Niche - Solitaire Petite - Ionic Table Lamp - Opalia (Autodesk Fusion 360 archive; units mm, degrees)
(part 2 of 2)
derived_base_feature "Derived Base Feature" bodies "E26 Base"
named bodies: "E26 Base"

design "Chinois"
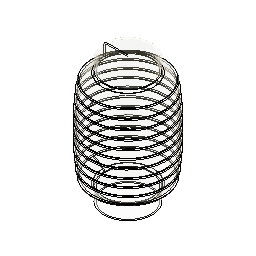
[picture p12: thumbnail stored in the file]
named bodies: "Chinois"

design "2-Pole Plug End"
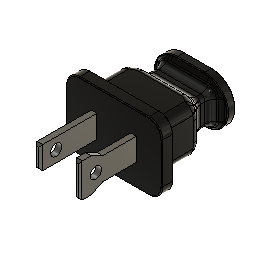
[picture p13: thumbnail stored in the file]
sketch "Sketch1" plane through (0, 0, 0) normal (0, 1, 0) x axis (1, 0, 0)
  line L1 (9.6837, 9.525) -> (-9.6837, 9.525)
  line L2 (13.4938, -5.715) -> (13.4938, 5.715)
  line L3 (-9.6837, -9.525) -> (9.6837, -9.525)
  line L4 (-13.4937, 5.715) -> (-13.4937, -5.715)
  line L5 (13.4938, -9.525) -> (-13.4937, 9.525)
  line L6 (-13.4937, -9.525) -> (13.4938, 9.525)
  arc A1 centre (-9.6837, -5.715) radius 3.81 clockwise from (-9.6837, -9.525) to (-13.4937, -5.715)
  arc A2 centre (9.6837, -5.715) radius 3.81 clockwise from (13.4938, -5.715) to (9.6837, -9.525)
  arc A3 centre (9.6837, 5.715) radius 3.81 clockwise from (9.6837, 9.525) to (13.4938, 5.715)
  arc A4 centre (-9.6837, 5.715) radius 3.81 clockwise from (-13.4937, 5.715) to (-9.6837, 9.525)
  point P6 (0, 0)
  point P1 (0, 0)
  point P5 (-13.4937, -9.525)
  point P4 (13.4938, -9.525)
  point P3 (13.4938, 9.525)
  point P2 (-13.4937, 9.525)
  horizontal L1
  perpendicular L1 L2
  parallel L1 L3
  parallel L2 L4
  coincident L5 P6
  coincident L6 P6
  coincident P1 P6
  coincident P5 L4
  coincident P5 L3
  tangent L4 A1
  tangent L3 A1
  coincident P4 L3
  coincident P4 L2
  tangent L3 A2
  tangent L2 A2
  equal A1 A2
  coincident P3 L2
  coincident P3 L1
  tangent L2 A3
  tangent L1 A3
  equal A1 A3
  coincident P2 L1
  coincident P2 L4
  tangent L1 A4
  tangent L4 A4
  equal A1 A4
  dimension "d1" distance P4 P5 = 26.9875
  dimension "d2" distance P2 P5 = 19.05
  dimension "d3" radius A1 = 3.81
extrude "Extrude1" new body sketch "Sketch1" profile of L1 L2 L3 L4 A1 A2 A3 A4 along normal blind 3.175
sketch "Sketch2" plane through (0, 3.175, 0) normal (0, 1, 0) x axis (-1, 0, 0)
  line L1 (9.6837, -9.525) -> (-9.6837, -9.525)
  line L2 (13.4937, 5.715) -> (13.4937, -5.715)
  line L3 (-9.6837, 9.525) -> (9.6837, 9.525)
  line L4 (-13.4938, -5.715) -> (-13.4938, 5.715)
  line L5 (10.16, -6.35) -> (-10.16, -6.35)
  line L6 (10.16, 6.35) -> (10.16, -6.35)
  line L7 (-10.16, 6.35) -> (10.16, 6.35)
  line L8 (-10.16, -6.35) -> (-10.16, 6.35)
  line L9 (10.16, 6.35) -> (-10.16, -6.35)
  line L10 (-10.16, 6.35) -> (10.16, -6.35)
  arc A1 centre (-9.6837, -5.715) radius 3.81 clockwise from (-9.6837, -9.525) to (-13.4938, -5.715)
  arc A2 centre (9.6837, -5.715) radius 3.81 clockwise from (13.4937, -5.715) to (9.6837, -9.525)
  arc A3 centre (9.6837, 5.715) radius 3.81 clockwise from (9.6837, 9.525) to (13.4937, 5.715)
  arc A4 centre (-9.6837, 5.715) radius 3.81 clockwise from (-13.4938, 5.715) to (-9.6837, 9.525)
  point P18 (0, 0)
  point P1 (0, 0)
  horizontal L5
  perpendicular L5 L6
  parallel L5 L7
  parallel L6 L8
  coincident L9 P18
  coincident L10 P18
  coincident P1 P18
extrude "Extrude2" add sketch "Sketch2" profile of L5 L6 L7 L8 along normal blind 9.525
sketch "Sketch3" plane through (0, 12.7, 0) normal (0, 1, 0) x axis (-1, 0, 0)
  line L1 (-10.16, -6.35) -> (-10.16, 6.35)
  line L2 (10.16, -6.35) -> (-10.16, -6.35)
  line L3 (10.16, 6.35) -> (10.16, -6.35)
  line L4 (-10.16, 6.35) -> (10.16, 6.35)
  line L5 (-7.1437, 3.9688) -> (7.1437, 3.9688)
  line L6 (-7.1437, -3.9688) -> (-7.1437, 3.9688)
  line L7 (7.1437, -3.9688) -> (-7.1437, -3.9688)
  line L8 (7.1437, 3.9688) -> (7.1437, -3.9688)
  line L9 (-7.1437, -3.9688) -> (7.1437, 3.9688)
  line L10 (7.1437, -3.9688) -> (-7.1437, 3.9688)
  point P10 (0, 0)
  point P1 (0, 0)
  point P8 (-7.1437, -3.9688)
  point P9 (7.1437, -3.9688)
  point P7 (-7.1437, 3.9688)
  horizontal L5
  perpendicular L5 L6
  parallel L5 L7
  parallel L6 L8
  coincident L9 P10
  coincident L10 P10
  coincident P1 P10
  dimension "d8" distance P8 P9 = 14.2875
  dimension "d9" distance P7 P8 = 7.9375
extrude "Extrude3" add sketch "Sketch3" profile of L5 L6 L7 L8 along normal blind 11.1125
fillet "Fillet1" radius 2.286 1.27 0.254
chamfer "Chamfer1" distance 3.429
fillet "Fillet2" radius 2.54 1.905
sketch "Sketch4" plane through (0, 23.8125, 0) normal (0, 1, 0) x axis (-1, 0, 0)
  line L1 (-7.1437, -2.6987) -> (-7.1437, 2.6987)
  line L2 (5.8737, -3.9688) -> (-5.8737, -3.9688)
  line L3 (7.1437, 2.6987) -> (7.1437, -2.6987)
  line L4 (-5.8737, 3.9688) -> (5.8737, 3.9688)
  line L5 (-3.81, 6.604) -> (3.81, 6.604)
  line L6 (3.81, -6.604) -> (-3.81, -6.604)
  line L7 (-10.414, 0) -> (10.414, 0)
  arc A1 centre (-5.8737, 2.6987) radius 1.27 clockwise from (-7.1437, 2.6987) to (-5.8737, 3.9688)
  arc A2 centre (-5.8737, -2.6987) radius 1.27 clockwise from (-5.8737, -3.9688) to (-7.1437, -2.6987)
  arc A3 centre (5.8737, -2.6987) radius 1.27 clockwise from (7.1437, -2.6987) to (5.8737, -3.9688)
  arc A4 centre (5.8737, 2.6987) radius 1.27 clockwise from (5.8737, 3.9688) to (7.1437, 2.6987)
  arc A5 centre (-3.81, 0) radius 6.604 clockwise from (-3.81, -6.604) to (-3.81, 6.604)
  arc A6 centre (3.81, 0) radius 6.604 clockwise from (3.81, 6.604) to (3.81, -6.604)
  point P20 (10.414, 0)
  point P21 (-10.414, 0)
  tangent L5 A5
  tangent A5 L6
  parallel L5 L6
  tangent L6 A6
  tangent L5 A6
  midpoint A6 P20
  midpoint A5 P21
  perpendicular L1 L7
extrude "Extrude4" add sketch "Sketch4" profile of A1 L1 A2 L2 A3 L3 A4 L4 L5 A5 L6 A6 against normal blind 2.286
chamfer "Chamfer2" distance 1.778
fillet "Fillet3" radius 1.778
fillet "Fillet4" radius 0.254
fillet "Fillet5" radius 0.254
fillet "Fillet6" radius 0.254
fillet "Fillet7" radius 3.175
sketch "Sketch5" plane through (0, 0, 0) normal (0, -1, 0) x axis (1, 0, 0)
  line L1 (-13.2397, -5.715) -> (-13.2397, 5.715)
  line L2 (9.6837, -9.271) -> (-9.6837, -9.271)
  line L3 (13.2397, 5.715) -> (13.2397, -5.715)
  line L4 (-9.6837, 9.271) -> (9.6837, 9.271)
  line L5 (-6.35, -3.175) -> (-6.35, 3.175)
  line L6 (6.35, 3.175) -> (-6.35, -3.175)
  line L7 (-6.35, 3.175) -> (6.35, -3.175)
  line L8 (-4.7625, 3.175) -> (-6.35, 3.175)
  line L9 (-4.7625, -3.175) -> (-4.7625, 3.175)
  line L10 (-6.35, -3.175) -> (-4.7625, -3.175)
  line L11 (-6.35, 3.175) -> (-6.35, -3.175)
  line L12 (0, -3.302) -> (0, 3.81)
  line L13 (4.7625, -3.175) -> (4.7625, 3.175)
  line L14 (4.7625, 3.175) -> (6.35, 3.175)
  line L15 (6.35, -3.175) -> (6.35, 3.175)
  line L16 (6.35, -3.175) -> (4.7625, -3.175)
  arc A1 centre (-9.6837, 5.715) radius 3.556 clockwise from (-13.2397, 5.715) to (-9.6837, 9.271)
  arc A2 centre (-9.6837, -5.715) radius 3.556 clockwise from (-9.6837, -9.271) to (-13.2397, -5.715)
  arc A3 centre (9.6837, -5.715) radius 3.556 clockwise from (13.2397, -5.715) to (9.6837, -9.271)
  arc A4 centre (9.6837, 5.715) radius 3.556 clockwise from (9.6837, 9.271) to (13.2397, 5.715)
  point P18 (0, 0)
  point P1 (0, 0)
  point P14 (-6.35, -3.175)
  point P27 (6.35, -3.175)
  point P17 (-6.35, 3.175)
  point P26 (6.35, 3.175)
  point P19 (-4.7625, 3.175)
  point P24 (4.7625, 3.175)
  point P20 (-4.7625, -3.175)
  point P25 (4.7625, -3.175)
  point P21 (-6.35, -3.175)
  point P28 (6.35, -3.175)
  point P15 (6.35, -3.175)
  point P16 (6.35, 3.175)
  coincident L6 P18
  coincident L7 P18
  coincident P1 P18
  horizontal L8
  vertical L9
  horizontal L10
  vertical L11
  vertical L12
  symmetric P14 L12 P27
  symmetric P17 L12 P26
  symmetric P19 L12 P24
  symmetric P20 L12 P25
  symmetric P21 L12 P28
  dimension "d36" distance P15 P16 = 6.35
  dimension "d37" distance P17 P19 = 1.5875
extrude "Extrude5" add sketch "Sketch5" profile of L5 L8 L9 L10 L11 L13 L14 L15 L16 along normal blind 15.875
sketch "Sketch7" plane through (0, 0, 3.175) normal (0, 0, 1) x axis (-1, 0, 0)
  line L1 (-4.7625, 0) -> (-6.35, 0)
  line L2 (-4.7625, 15.875) -> (-4.7625, 0)
  line L3 (-6.35, 15.875) -> (-4.7625, 15.875)
  line L4 (-6.35, 0) -> (-6.35, 15.875)
  line L5 (-4.7625, 15.875) -> (-6.35, 15.875)
  line L6 (-4.7625, 9.525) -> (-4.7625, 15.875)
  line L7 (-6.35, 9.525) -> (-4.7625, 9.525)
  line L8 (-6.35, 15.875) -> (-6.35, 9.525)
  point P5 (-6.35, 15.875)
  point P6 (-6.35, 15.875)
  point P9 (-6.35, 9.525)
  horizontal L5
  vertical L6
  horizontal L7
  vertical L8
  coincident P5 P6
  dimension "d45" distance P6 P9 = 6.35
extrude "Extrude7" add sketch "Sketch7" profile of L2 L3 L4 L5 L6 L7 L8 against normal blind 7.9375 and along normal blind 1.5875
chamfer "Chamfer3" distance 0.508
chamfer "Chamfer4" distance 0.635 distance 0.635
sketch "Sketch6" plane through (6.35, 0, 0) normal (1, 0, 0) x axis (0, 1, 0)
  line L1 (0, -3.175) -> (-9.525, -3.175)
  line L2 (0, 3.175) -> (0, -3.175)
  line L3 (-9.525, 3.175) -> (0, 3.175)
  line L4 (-15.367, -4.6355) -> (-15.367, 4.6355)
  line L5 (-11.43, 0) -> (-16.002, 0)
  line L6 (-9.525, -4.7625) -> (-15.24, -4.7625)
  line L7 (-9.525, -3.175) -> (-9.525, -4.7625)
  line L8 (-9.525, 4.7625) -> (-9.525, 3.175)
  line L9 (-15.24, 4.7625) -> (-9.525, 4.7625)
  line L10 (-15.24, -4.7625) -> (-15.367, -4.6355)
  line L11 (-15.367, 4.6355) -> (-15.24, 4.7625)
  circle C1 centre (-11.43, 0) radius 1.5875
  point P9 (-11.43, 0)
  point P10 (-11.43, 0)
  perpendicular L4 L5
  coincident P9 P10
  dimension "d42" diameter C1 = 3.175
extrude "Extrude6" cut sketch "Sketch6" profile of C1 against normal blind 20.32
chamfer "Chamfer5" distance 3.175 distance 1.5875 distance 3.175 distance 1.5875
component_from_bodies "Body->Comp"
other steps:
base_feature "Base Feature" bodies "2-Pole Plug End"
create_component "CreateComponent1"
remove_body "RemoveBody1"
named bodies: "2-Pole Plug End"

design "Marble Base - Plastic Insert"
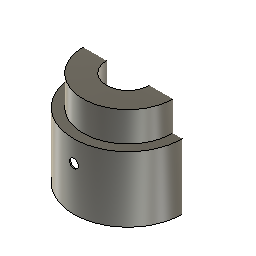
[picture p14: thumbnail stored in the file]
sketch "Sketch1" plane through (0, 0, 0) normal (0, 0, 1) x axis (1, 0, 0)
  circle C1 centre (0, 0) radius 50.038
  point P1 (0, 0)
  point P2 (0, 0)
  coincident P1 P2
  dimension "d1" diameter C1 = 100.076
extrude "Extrude1" new body sketch "Sketch1" along normal blind 72.898 bodies "Plastic Insert"
shell "Shell1" innerThickness 1.016
work_plane "WorkPlane1" AlongDistance 18.034
sketch "Sketch2" plane through (0, 0, 90.932) normal (0, 0, 1) x axis (1, 0, 0)
  circle C1 centre (0, 0) radius 20.701
  point P1 (0, 0)
  point P2 (0, 0)
  coincident P1 P2
  dimension "d6" diameter C1 = 41.402
extrude "Extrude2" add sketch "Sketch2" against normal blind 65.024
shell "Shell2" innerThickness 1.016
sketch "Sketch3" plane through (0, 0, 0) normal (0, 1, 0) x axis (1, 0, 0)
  line L1 (5.08, -20.32) -> (-5.08, -20.32)
  line L2 (5.08, 20.32) -> (5.08, -20.32)
  line L3 (-5.08, 20.32) -> (5.08, 20.32)
  line L4 (-5.08, -20.32) -> (-5.08, 20.32)
  line L5 (5.08, 20.32) -> (-5.08, -20.32)
  line L6 (-5.08, 20.32) -> (5.08, -20.32)
  point P6 (0, 0)
  point P1 (0, 0)
  horizontal L1
  perpendicular L1 L2
  parallel L1 L3
  parallel L2 L4
  coincident L5 P6
  coincident L6 P6
  coincident P1 P6
extrude "Extrude3" cut sketch "Sketch3" profile of L1 L2 L3 L4 along normal blind 91.44
sketch "Sketch4" plane through (0, 0, 0) normal (0, 1, 0) x axis (1, 0, 0)
  line L1 (0, -40.64) -> (0, 0)
  circle C1 centre (0, -40.64) radius 4.064
  point P1 (0, 0)
  point P2 (0, 0)
  point P3 (0, -40.64)
  point P4 (0, -40.64)
  coincident P1 P2
  vertical L1
  coincident P3 P4
  dimension "d12" diameter C1 = 8.128
work_plane "WorkPlane2" AlongDistance -91.44
sketch "Sketch5" plane through (0, -91.44, 0) normal (0, 1, 0) x axis (1, 0, 0)
  circle C1 centre (0, -40.64) radius 4.064
extrude "Extrude4" cut sketch "Sketch5" along normal blind 63.5
sketch "Sketch6" plane through (0, 0, 26.924) normal (0, 0, 1) x axis (-1, 0, 0)
  circle C1 centre (0, 0) radius 19.685
  circle C2 centre (0, 0) radius 5.461
  concentric C1 C2
  dimension "d16" diameter C2 = 10.922
extrude "Extrude5" cut sketch "Sketch6" profile of C2 against normal blind 15.24
sketch "Sketch7" plane through (0, 0, 72.898) normal (0, 0, 1) x axis (-1, 0, 0)
  circle C1 centre (0, 0) radius 20.701
  circle C2 centre (0, 0) radius 50.038
  circle C3 centre (0, 0) radius 20.701
  circle C4 centre (0, 0) radius 45.72
  point P1 (0, 0)
  point P3 (0, 0)
  point P4 (0, 0)
  coincident P1 P3
  coincident P1 P4
extrude "Extrude6" add sketch "Sketch7" profile of C1 C3 C4 along normal blind 18.034
sketch "Sketch8" plane through (0, 0, 71.882) normal (0, 0, -1) x axis (1, 0, 0)
  circle C1 centre (0, 0) radius 20.701
  circle C2 centre (0, 0) radius 49.022
  circle C3 centre (0, 0) radius 20.701
  circle C4 centre (0, 0) radius 44.704
  point P1 (0, 0)
  point P3 (0, 0)
  point P4 (0, 0)
  coincident P1 P3
  coincident P1 P4
  dimension "d21" diameter C4 = 89.408
extrude "Extrude7" cut sketch "Sketch8" profile of C1 C3 C4 against normal blind 17.78
extrude "Extrude8" add of existing geometry blind 9.398
extrude "Extrude9" cut of existing geometry blind -9.398
component_from_bodies "Body->Comp"
offset_faces "OffsetFaces1" distance 4.445
offset_faces "OffsetFaces2" distance -4.445
offset_faces "OffsetFaces3" distance 3.175
offset_faces "OffsetFaces4" distance 3.175
offset_faces "OffsetFaces5" distance 3.175
offset_faces "OffsetFaces6" distance -3.175
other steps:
base_feature "Base Feature" bodies "Plastic Insert"
create_component "CreateComponent1"
remove_body "RemoveBody1"
named bodies: "Plastic Insert"

design "Rubber Grommet"
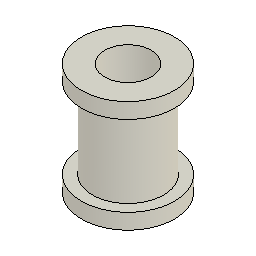
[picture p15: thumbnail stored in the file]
sketch "Sketch1" plane through (0, 0, 0) normal (0, 1, 0) x axis (1, 0, 0)
  line L1 (0, 3.048) -> (0, -12.7)
  line L2 (5.842, 0.508) -> (5.842, -12.7)
  line L3 (3.81, 3.048) -> (3.81, -15.24)
  line L4 (7.62, -12.7) -> (7.62, -15.24)
  line L5 (7.62, 3.048) -> (7.62, 0.508)
  line L6 (7.62, 0.508) -> (5.842, 0.508)
  line L7 (7.62, -12.7) -> (5.842, -12.7)
  line L8 (7.62, -15.24) -> (3.81, -15.24)
  line L9 (7.62, 3.048) -> (3.81, 3.048)
  vertical L1
  collinear L4 L5
revolve "Revolve1" sketch "Sketch1" AlongAngle 360 bodies "Rubber Grommet"
component_from_bodies "Body->Comp"
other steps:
base_feature "Base Feature" bodies "Rubber Grommet"
create_component "CreateComponent1"
remove_body "RemoveBody1"
named bodies: "Rubber Grommet"

design "Trove - TL"
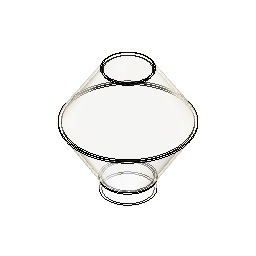
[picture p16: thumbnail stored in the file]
derived_base_feature "Derived Base Feature" bodies "Trove"
hole "Hole1" HoleDepth 88.9 HoleDiameter 44.45 TipAngle 118
sketch "Sketch1" plane through (0, 0, 0) normal (1, 0, 0) x axis (0, 1, 0)
  line L1 (0, 243.0601) -> (0, 247.8226)
  line L2 (-50.8, -12.7122) -> (-50.8, 10.9447)
  line L3 (0, -25.4) -> (0, 243.0601)
  line L4 (-46.0375, -12.7122) -> (-50.8, -12.7122)
  line L5 (-46.0375, -12.7122) -> (-46.0375, 12.3043)
  line L6 (-45.9716, 247.8226) -> (0, 247.8226)
  line L7 (-43.3841, 243.0601) -> (0, 243.0601)
  line L8 (-122.8321, 128.6352) -> (-51.757, 14.2971)
  line L9 (-117.1907, 128.5808) -> (-46.9945, 15.6567)
  line L10 (-48.6353, 246.3754) -> (-122.7993, 132.0392)
  line L11 (-46.0478, 241.6129) -> (-117.1579, 131.9848)
  arc A1 centre (-57.15, 10.9447) radius 6.35 clockwise from (-51.757, 14.2971) to (-50.8, 10.9447)
  arc A2 centre (-52.3875, 12.3043) radius 6.35 clockwise from (-46.9945, 15.6567) to (-46.0375, 12.3043)
  arc A3 centre (-114.4942, 130.257) radius 3.175 between (-117.1579, 131.9848) and (-117.1907, 128.5808)
  arc A4 centre (-120.1356, 130.3114) radius 3.175 between (-122.7993, 132.0392) and (-122.8321, 128.6352)
  arc A5 centre (-45.9716, 244.6476) radius 3.175 between (-45.9716, 247.8226) and (-48.6353, 246.3754)
  arc A6 centre (-43.3841, 239.8851) radius 3.175 clockwise from (-46.0478, 241.6129) to (-43.3841, 243.0601)
  point P3 (0, 247.8226)
  point P4 (0, 243.0601)
  vertical L1
  vertical L3
  tangent L5 A2
  perpendicular L1 L6
  perpendicular L1 L7
  tangent L11 A3
  tangent L9 A3
  tangent L10 A4
  tangent L8 A4
  equal A3 A4
  tangent L6 A5
  tangent L10 A5
  tangent L11 A6
  tangent L7 A6
  dimension "d8" distance P3 P4 = 4.7625
  dimension "d11" radius A2 = 6.35
  dimension "d15" radius A3 = 3.175
  dimension "d16" radius A5 = 3.175
  dimension "d17" radius A6 = 3.175
revolve "Revolve1" sketch "Sketch1" AlongAngle 180 bodies "Trove - TL"
revolve "Revolve2" sketch "Sketch1" AlongAngle -180
component_from_bodies "Body->Comp"
remove_body "RemoveBody2"
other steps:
base_feature "Base Feature" bodies "Trove - TL"
create_component "CreateComponent1"
remove_body "RemoveBody1"
named bodies: "Trove", "Trove - TL"

design "T9-5In"
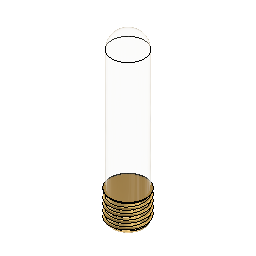
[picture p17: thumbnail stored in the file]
sketch "Sketch1" plane through (0, 0, 0) normal (0, 1, 0) x axis (1, 0, 0)
  line L1 (0, 0) -> (0, -127)
  line L2 (12.7, -127) -> (-12.7, -127)
  line L3 (12.7, -12.7) -> (12.7, -127)
  line L4 (-12.7, -127) -> (-12.7, -12.7)
  arc A1 centre (0, -12.7) radius 12.7 clockwise from (-12.7, -12.7) to (12.7, -12.7)
  point P1 (0, 0)
  point P3 (0, 0)
  coincident P1 P3
  vertical L1
  horizontal L2
  vertical L3
  vertical L4
revolve "Revolve1" sketch "Sketch1" AlongAngle 360 bodies "BU-T10-5-LED-120V"
derived_base_feature "Derived Base Feature" bodies "E26 Base"
move "Move1"
component_from_bodies "Body->Comp"
copy_paste "CutPaste"
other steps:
base_feature "Base Feature" bodies "BU-T10-5-LED-120V"
create_component "CreateComponent1"
create_component "CreateComponent2"
remove_body "RemoveBody1"
remove_instance "RemoveInstance1"
named bodies: "BU-T10-5-LED-120V", "E26 Base"

design "Orb 8.5In - Solitaire Petite"
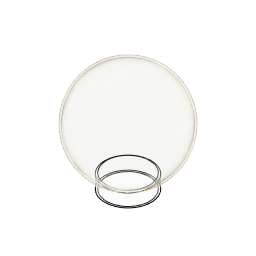
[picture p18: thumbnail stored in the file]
sketch "Sketch1" plane through (0, 0, 0) normal (0, 1, 0) x axis (1, 0, 0)
  line L1 (0, 190.5) -> (0, -127)
  line L2 (50.8, 190.5) -> (50.8, -127)
  line L3 (-50.8, 190.5) -> (-50.8, -127)
  line L4 (50.8, 95.25) -> (-50.8, 95.25)
  line L5 (50.8, 123.825) -> (-50.8, 123.825)
  line L6 (101.6, -107.95) -> (0, -107.95)
  circle C1 centre (0, 0) radius 107.95
  point P1 (0, 0)
  point P2 (0, 0)
  point P5 (50.8, -127)
  point P7 (-50.8, -127)
  point P6 (50.8, 190.5)
  point P8 (-50.8, 190.5)
  point P9 (-50.8, 95.25)
  point P10 (50.8, 95.25)
  point P13 (0, -107.95)
  coincident P1 P2
  vertical L1
  symmetric L1 P5 P7
  symmetric L1 P6 P8
  coincident C1 P9
  coincident L3 P9
  coincident C1 P10
  coincident L2 P10
  perpendicular L2 L4
  coincident C1 P13
  coincident L1 P13
  tangent C1 L6
  dimension "d1" diameter C1 = 215.9
  dimension "d2" = 50.8
  dimension "d4" = -28.575
revolve "Revolve1" sketch "Sketch1" AlongAngle 360 bodies "Orb-8.5"
shell "Shell1" innerThickness 3.81
component_from_bodies "Body->Comp"
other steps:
base_feature "Base Feature" bodies "Orb-8.5"
create_component "CreateComponent1"
remove_body "RemoveBody1"
named bodies: "Orb-8.5"

design "Dart"
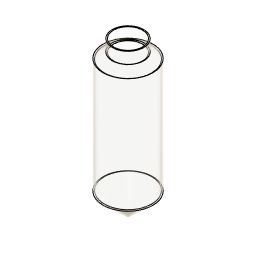
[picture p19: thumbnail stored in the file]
sketch "Sketch1" plane through (0, 0, 0) normal (0, 0, 1) x axis (1, 0, 0)
work_plane "WorkPlane1" AlongDistance 76.2
sketch "Sketch2" plane through (0, 0, 76.2) normal (0, 0, 1) x axis (1, 0, 0)
sketch "Sketch3" plane through (0, 0, 76.2) normal (0, 0, 1) x axis (1, 0, 0)
sketch "Sketch4" plane through (0, 0, 76.2) normal (0, 0, 1) x axis (1, 0, 0)
  circle C1 centre (0, 0) radius 82.55
  point P1 (0, 0)
  point P2 (0, 0)
  coincident P1 P2
  dimension "d2" diameter C1 = 165.1
loft "Loft1" sketch "Sketch4" bodies "Dart Grand"
extrude "Extrude1" add of existing geometry blind 381
work_plane "WorkPlane2" AlongDistance 19.05
sketch "Sketch5" plane through (0, 0, 476.25) normal (0, 0, 1) x axis (1, 0, 0)
  circle C1 centre (0, 0) radius 52.07
  point P1 (0, 0)
  point P2 (0, 0)
  coincident P1 P2
  dimension "d6" diameter C1 = 104.14
loft "Loft2" sketch "Sketch5"
extrude "Extrude2" add of existing geometry blind 38.1
shell "Shell3" innerThickness 3.81
component_from_bodies "Body->Comp"
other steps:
base_feature "Base Feature" bodies "Dart Grand"
create_component "CreateComponent1"
remove_body "RemoveBody1"
named bodies: "Dart Grand"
